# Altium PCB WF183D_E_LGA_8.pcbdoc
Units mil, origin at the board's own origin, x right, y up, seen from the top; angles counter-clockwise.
Board outline 684.13 x 661.77 mil, 2 copper layers (Top Layer, Bottom Layer); 1 components, 0 nets, 8 pads, 0 vias.
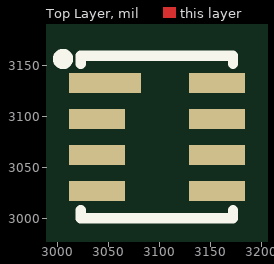
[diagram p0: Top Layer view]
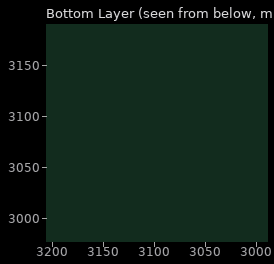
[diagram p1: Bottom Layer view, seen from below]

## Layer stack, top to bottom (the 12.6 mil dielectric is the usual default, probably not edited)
Top Layer: signal copper (thickness not stored)
Dielectric: dielectric 12.6, FR-4, Dk 4.8
Bottom Layer: signal copper (thickness not stored)

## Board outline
3434.13,2750 2750,2750 2750,3411.77 3434.13,3411.77

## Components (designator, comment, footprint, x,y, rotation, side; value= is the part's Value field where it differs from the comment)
? "LGA-8_L3.8-W3.6-P0.90-TL" LGA-8_L3.8-W3.6-P0.90-TL 3097.51,3080 r0 top

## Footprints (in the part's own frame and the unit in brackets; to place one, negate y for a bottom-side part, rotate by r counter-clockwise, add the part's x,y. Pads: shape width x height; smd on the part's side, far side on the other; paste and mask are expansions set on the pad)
LGA-8_L3.8-W3.6-P0.90-TL [mm]
  rect 1.8x0.5 smd paste+0 mask+0.05: 1(-1.3,1.35)
  rect 1.4x0.5 smd paste+0 mask+0.05: 2(-1.5,0.45) 3(-1.5,-0.45) 4(-1.5,-1.35) 5(1.5,-1.35) 6(1.5,-0.45) 7(1.5,0.45) 8(1.5,1.35)
  silkscreen extent -2.48,-2.03 1.91,2.08

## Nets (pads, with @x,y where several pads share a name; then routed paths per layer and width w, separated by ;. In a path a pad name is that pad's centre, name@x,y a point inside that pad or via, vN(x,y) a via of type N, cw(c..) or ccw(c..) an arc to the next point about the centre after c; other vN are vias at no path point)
pads on no net: ?.1 ?.2 ?.3 ?.4 ?.5 ?.6 ?.7 ?.8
